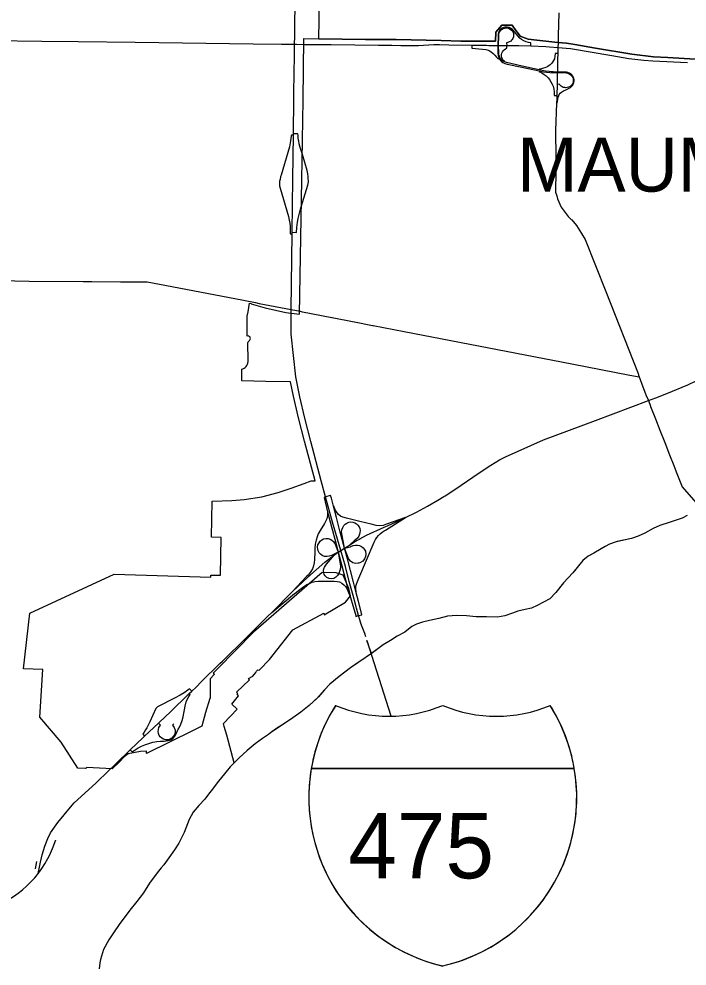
# Model space of a CAD drawing. Extents: x 0 to 750, y 0 to 507.
# Drawn here: x 229.9 to 276.3, y 149.3 to 215 of the extents above; entities that cross this region are included whole.
import ezdxf

# ---------------------------------------------------------------- set-up
doc = ezdxf.new("R2010")
doc.units = 0
for name, color, linetype in [('DV_X_Corp_Line', 7, 'Continuous'), ('GM_X_Corporation_Text', 7, 'Continuous'), ('GM_X_County', 7, 'Continuous'), ('GM_X_Interchange_Ramps', 7, 'Continuous'), ('GM_X_Interstate_Route', 7, 'Continuous'), ('GM_X_Rail_Line', 7, 'Continuous'), ('GM_X_US_Route', 7, 'Continuous')]:
    doc.layers.add(name, color=color, linetype=linetype)

msp = doc.modelspace()

# ---------------------------------------------------------------- linework, layer by layer
at = {"layer": 'DV_X_Corp_Line'}
for points in [[(277.58, 212.124), (274.932, 212.279), (273.94, 212.324), (272.425, 212.512), (269.916, 212.931), (268.479, 213.175), (267.91, 213.278), (267.311, 213.321), (265.848, 213.475), (265.244, 213.563), (264.866, 213.703), (264.697, 213.771), (264.564, 213.913), (264.382, 214.161), (264.137, 214.52), (263.427, 214.529), (263.001, 214.043), (262.967, 213.425), (260.563, 213.423), (259.202, 213.461), (256.08, 213.529), (253.965, 213.526), (250.728, 213.571), (250.775, 216.198)], [(276.279, 180.529), (275.922, 180.353), (275.013, 180.042), (274.386, 179.848), (273.909, 179.643), (273.335, 179.308), (272.872, 179.097), (272.407, 178.947), (271.468, 178.741), (271.428, 178.732), (271.278, 178.683), (270.876, 178.553), (270.585, 178.396), (269.8, 177.934), (269.402, 177.717), (269.028, 177.41), (268.729, 177.047), (268.466, 176.709), (268.349, 176.559), (267.696, 175.864), (267.153, 175.198), (266.758, 174.761), (265.878, 174.294), (265.466, 174.118), (265.03, 174.023), (264.524, 173.893), (264.152, 173.762), (263.625, 173.572), (263.109, 173.493), (262.354, 173.501), (261.644, 173.514), (260.97, 173.572), (260.29, 173.595), (259.655, 173.557), (259.058, 173.393), (258.407, 173.25), (257.905, 173.135), (257.494, 173.009), (257.172, 172.832), (256.688, 172.441), (256.159, 172.161), (255.696, 171.88), (255.183, 171.57), (254.361, 170.947), (253.529, 170.396), (252.915, 169.985), (252.133, 169.377), (251.492, 168.843), (251.112, 168.456), (250.585, 167.86), (250.06, 167.374), (249.475, 166.899), (248.91, 166.499), (248.49, 166.216), (248.331, 166.109), (247.469, 165.531), (247.232, 165.359), (246.809, 165.083), (246.305, 164.702), (245.75, 164.242), (245.204, 163.746), (244.845, 163.383), (244.334, 165.314), (244.149, 165.919), (244.109, 166.124), (245.056, 167.108), (244.695, 167.455), (245.161, 168.031), (245.042, 168.153), (245.096, 168.206), (245.023, 168.281), (245.922, 169.151), (245.848, 169.227), (246.148, 169.396), (246.36, 169.66), (246.393, 169.754), (246.503, 169.83), (246.597, 169.802), (246.597, 169.839), (247.304, 170.547), (248.919, 172.617), (251.077, 173.765), (251.083, 173.64), (252.564, 174.531), (252.916, 174.966), (252.8, 175.472), (252.405, 176.395), (251.933, 176.568), (250.96, 176.595), (246.203, 172.449), (243.694, 169.916), (243.39, 169.606), (243.456, 169.557), (243.471, 169.52), (243.176, 169.209), (243.176, 167.881), (243.156, 167.858), (242.87, 166.873), (242.613, 165.938), (242.003, 165.632), (238.774, 164.046), (238.777, 164.189), (238.365, 164.183), (237.507, 164.003), (237.223, 163.803), (236.871, 163.43), (236.389, 162.984), (234.624, 163.064), (234.591, 163.026), (234.526, 162.996), (233.997, 163.012), (232.849, 164.816), (231.372, 166.563), (231.578, 169.854), (230.229, 169.91), (230.671, 173.758), (236.519, 176.479), (243.237, 176.261), (243.237, 176.391), (243.908, 176.391), (243.958, 179), (243.284, 179.023), (243.329, 181.538), (244.697, 181.579), (245.548, 181.638), (246.773, 181.821), (247.905, 182.133), (248.816, 182.42), (249.711, 182.758), (250.192, 182.946), (250.46, 182.94), (249.733, 185.697), (249.314, 187.306), (248.963, 188.804), (248.749, 189.802), (247.04, 189.832), (245.383, 189.861), (245.383, 190.673), (245.462, 190.703), (245.533, 190.742), (245.603, 190.793), (245.675, 190.865), (245.729, 190.939), (245.769, 191.014), (245.801, 191.102), (245.822, 191.211), (245.824, 191.292), (245.822, 191.324), (245.802, 192.454), (245.802, 192.479), (245.808, 192.519), (245.82, 192.559), (245.84, 192.598), (245.866, 192.633), (245.887, 192.654), (245.919, 192.677), (245.943, 192.704), (245.962, 192.74), (245.971, 192.767), (245.975, 192.81), (245.967, 192.857), (245.952, 192.892), (245.93, 192.923), (245.902, 192.948), (245.859, 192.97), (245.816, 192.98), (245.764, 192.977), (245.745, 194.094), (245.745, 194.231), (245.753, 194.36), (245.82, 194.653), (245.916, 195.255), (246.022, 195.236), (246.02, 195.211), (247.003, 194.929), (248.434, 194.597), (249.39, 194.496), (249.54, 203.782), (249.626, 209.321), (249.682, 213.598), (250.728, 213.571), (253.965, 213.526), (256.08, 213.529), (259.202, 213.461), (260.563, 213.423), (262.967, 213.425), (263.001, 214.043), (263.427, 214.529), (264.137, 214.52), (264.382, 214.161), (264.564, 213.913), (264.697, 213.771), (264.866, 213.703), (265.244, 213.563), (265.848, 213.475), (267.311, 213.321), (267.91, 213.278), (268.479, 213.175), (269.916, 212.931), (272.425, 212.512), (273.94, 212.324), (274.932, 212.279), (277.58, 212.124)]]:
    msp.add_lwpolyline(points, dxfattribs=at)
at = {"layer": 'GM_X_County'}
msp.add_lwpolyline([(276.279, 180.529), (275.922, 180.353), (275.013, 180.042), (274.386, 179.848), (273.909, 179.643), (273.335, 179.308), (272.872, 179.097), (272.406, 178.947), (271.428, 178.732), (270.876, 178.553), (270.585, 178.396), (269.915, 177.997), (269.402, 177.717), (269.028, 177.41), (268.729, 177.047), (268.349, 176.559), (267.696, 175.864), (267.153, 175.198), (266.758, 174.761), (265.878, 174.294), (265.466, 174.118), (265.03, 174.023), (264.524, 173.893), (264.152, 173.762), (263.625, 173.572), (263.109, 173.493), (262.354, 173.501), (261.644, 173.514), (260.97, 173.572), (260.29, 173.595), (259.655, 173.557), (259.058, 173.393), (258.407, 173.25), (257.905, 173.135), (257.494, 173.009), (257.172, 172.832), (256.688, 172.441), (256.159, 172.161), (255.696, 171.88), (255.183, 171.57), (254.385, 170.966), (253.565, 170.42), (253.425, 170.326), (252.915, 169.985), (252.133, 169.377), (251.492, 168.843), (251.112, 168.456), (250.702, 167.968), (250.06, 167.374), (249.475, 166.899), (248.91, 166.499), (248.331, 166.109), (247.797, 165.769), (247.469, 165.531), (247.232, 165.359), (246.809, 165.083), (246.305, 164.702), (245.75, 164.242), (245.204, 163.746), (244.845, 163.383), (244.567, 163.101), (244.176, 162.634), (243.765, 162.117), (243.263, 161.44), (243.082, 161.209), (242.811, 160.863), (242.406, 160.442), (242.006, 159.959), (241.74, 159.456), (241.38, 158.557), (241.017, 157.829), (240.716, 157.37), (240.32, 156.798), (239.969, 156.33), (239.787, 156.105), (239.503, 155.754), (238.975, 155.037), (238.572, 154.385), (238.09, 153.783), (237.608, 153.176), (236.867, 152.176), (236.485, 151.604), (236.155, 151.111), (235.777, 150.458), (235.574, 149.768), (235.544, 149.53), (235.492, 149.117)], dxfattribs=at)
at = {"layer": 'GM_X_Interchange_Ramps'}
for points in [[(265.434, 213.085), (265.425, 213.31), (265.265, 213.335), (265.115, 213.368), (264.94, 213.433), (264.784, 213.529), (264.663, 213.629), (264.151, 214.221), (264.053, 214.299), (263.924, 214.364), (263.777, 214.395), (263.634, 214.388), (263.498, 214.348), (263.385, 214.288), (263.28, 214.197), (263.226, 214.103), (263.191, 214.019), (263.166, 213.901), (263.155, 213.796), (263.142, 213.118), (263.144, 212.561), (263.154, 212.448), (263.186, 212.326), (263.226, 212.239), (263.261, 212.17), (263.32, 212.081), (263.397, 212.006), (263.494, 211.94), (263.623, 211.879), (263.793, 211.824), (264.801, 211.611), (266.006, 211.357), (266.317, 211.292), (266.514, 211.26), (266.74, 211.241), (266.985, 211.231), (267.267, 211.239), (267.886, 211.217), (268.009, 211.193), (268.09, 211.156), (268.163, 211.106), (268.234, 211.045), (268.289, 210.974), (268.333, 210.893), (268.363, 210.798), (268.374, 210.707), (268.363, 210.608), (268.335, 210.503), (268.287, 210.405), (268.224, 210.343), (268.149, 210.274), (268.036, 210.223), (267.94, 210.203), (267.868, 210.191), (267.791, 210.193), (267.679, 210.207), (267.6, 210.25), (267.53, 210.304), (267.453, 210.375), (267.404, 210.434), (267.248, 210.422)], [(267.216, 209.11), (267.266, 209.109), (267.277, 209.242), (267.295, 209.4), (267.327, 209.541), (267.368, 209.649), (267.4, 209.725), (267.453, 209.802), (267.556, 209.883), (267.706, 209.966), (267.866, 210.037), (268.175, 210.201), (268.266, 210.292), (268.332, 210.367), (268.374, 210.444), (268.406, 210.543), (268.428, 210.654), (268.426, 210.758), (268.406, 210.841), (268.376, 210.924), (268.337, 210.996), (268.276, 211.079), (268.2, 211.15), (268.104, 211.205), (267.999, 211.241), (267.896, 211.26), (267.268, 211.275), (266.983, 211.286), (266.848, 211.294), (266.69, 211.304), (266.455, 211.332), (266.012, 211.426), (264.822, 211.693), (263.742, 211.935), (263.555, 211.998), (263.464, 212.055), (263.385, 212.136), (263.32, 212.225), (263.251, 212.355), (263.213, 212.468), (263.203, 212.579), (263.176, 213.118), (263.206, 213.774), (263.22, 213.896), (263.242, 214.007), (263.302, 214.114), (263.378, 214.201), (263.44, 214.246), (263.516, 214.293), (263.623, 214.326), (263.757, 214.335), (263.872, 214.31), (263.984, 214.259), (264.082, 214.183), (264.169, 214.081), (264.218, 213.958), (264.236, 213.845), (264.224, 213.718), (264.18, 213.606), (264.14, 213.531), (264.097, 213.475), (264.013, 213.399), (263.935, 213.361), (263.839, 213.328), (263.748, 213.308), (263.762, 213.115)], [(261.33, 213.142), (261.325, 212.928), (262.075, 212.871), (262.316, 212.836), (262.476, 212.782), (262.563, 212.741), (262.688, 212.674), (262.824, 212.565), (262.943, 212.452), (263.053, 212.31), (263.162, 212.197), (263.226, 212.239)], [(263.555, 211.998), (263.591, 212.047), (263.54, 212.083), (263.468, 212.164), (263.417, 212.274), (263.393, 212.385), (263.393, 212.49), (263.423, 212.595), (263.47, 212.682), (263.528, 212.763), (263.589, 212.814), (263.676, 212.883), (263.772, 212.927), (263.762, 213.115)], [(267.298, 212.558), (267.112, 212.563), (267.092, 212.369), (267.069, 212.182), (267.011, 212.069), (266.941, 211.964), (266.858, 211.869), (266.773, 211.772), (266.698, 211.723), (266.615, 211.67), (266.522, 211.616), (266.408, 211.563), (266.299, 211.533), (266.172, 211.5), (266.038, 211.486), (266.012, 211.426)], [(266.006, 211.357), (265.994, 211.303), (266.194, 211.229), (266.358, 211.116), (266.483, 211.017), (266.625, 210.869), (266.722, 210.75), (266.819, 210.594), (266.898, 210.446), (266.975, 210.286), (267.034, 210.086), (267.048, 209.902), (267.044, 209.729), (267.047, 209.655), (267.229, 209.65)], [(248.96, 206.892), (248.822, 206.894), (248.816, 206.833), (248.76, 206.496), (248.679, 206.086), (248.11, 204.117), (248.073, 204.032)], [(249.999, 203.675), (250.004, 203.75), (249.994, 203.86), (249.985, 204.032), (249.964, 204.217), (249.913, 204.439), (249.581, 205.559), (249.434, 206.053), (249.371, 206.288), (249.332, 206.485), (249.299, 206.689), (249.279, 206.91), (249.277, 206.997), (248.962, 207.001)], [(248.073, 204.032), (248.032, 203.824), (248.005, 203.708), (247.996, 203.561), (248.005, 203.395), (248.038, 203.228), (248.609, 201.268), (248.671, 201.003), (248.716, 200.811), (248.731, 200.59), (248.746, 200.065), (248.872, 200.064)], [(248.873, 200.168), (249.176, 200.164), (249.202, 200.494), (249.252, 200.862), (249.301, 201.132), (249.402, 201.591), (249.502, 201.923), (249.955, 203.436), (249.999, 203.675)], [(253.484, 173.592), (253.7, 173.656), (253.655, 173.862), (253.475, 174.57), (253.295, 175.278), (253.13, 175.925), (252.707, 177.523), (252.508, 178.275), (252.213, 179.39), (251.949, 180.389), (251.739, 181.186), (251.594, 181.74), (251.539, 181.914), (251.195, 181.819)], [(251.195, 181.819), (251.086, 181.784), (251.335, 180.787), (251.606, 179.747), (251.898, 178.645), (252.072, 177.992), (252.323, 177.047), (252.722, 175.544), (253.279, 173.592), (253.298, 173.529), (253.484, 173.592)], [(251.335, 180.787), (251.316, 180.782), (251.326, 180.677), (251.319, 180.53), (251.269, 180.31), (251.207, 180.163), (251.106, 179.979), (250.814, 179.505), (250.68, 179.254), (250.606, 179.047), (250.534, 178.818), (250.474, 178.542), (250.446, 178.278), (250.438, 178.01), (250.422, 177.489), (250.392, 177.247), (250.345, 177.04), (250.273, 176.838), (250.17, 176.642), (250.06, 176.483), (249.979, 176.406), (249.878, 176.303), (248.905, 175.263)], [(256.731, 180.4), (255.426, 179.937), (255.192, 179.851), (254.96, 179.823), (254.703, 179.847), (254.344, 179.924), (253.575, 180.112), (252.648, 180.339), (252.396, 180.42), (252.226, 180.496), (252.088, 180.597), (251.985, 180.714), (251.901, 180.854), (251.83, 180.997), (251.759, 181.192), (251.739, 181.186)], [(252.508, 178.275), (252.299, 179.413), (252.319, 179.552), (252.377, 179.711), (252.455, 179.841), (252.553, 179.94), (252.667, 180.01), (252.81, 180.068), (252.951, 180.086), (253.081, 180.076), (253.215, 180.026), (253.332, 179.956), (253.425, 179.867), (253.513, 179.751), (253.558, 179.638), (253.585, 179.504), (253.578, 179.361), (253.546, 179.237), (253.493, 179.102), (253.405, 178.975), (253.289, 178.866), (253.227, 178.815), (252.841, 178.482)], [(253.295, 175.278), (253.311, 175.282), (253.28, 175.426), (253.28, 175.517), (253.29, 175.634), (253.332, 175.777), (253.399, 175.967), (253.494, 176.189), (254.565, 178.691), (254.662, 178.874), (254.748, 179.001), (254.867, 179.144), (254.985, 179.267), (255.118, 179.371), (255.247, 179.466), (255.338, 179.52), (256.731, 180.4)], [(252.072, 177.992), (251.788, 177.856), (251.595, 177.762), (251.443, 177.706), (251.293, 177.682), (251.122, 177.7), (250.96, 177.755), (250.842, 177.849), (250.751, 177.953), (250.679, 178.077), (250.646, 178.205), (250.634, 178.349), (250.659, 178.492), (250.736, 178.647), (250.827, 178.761), (250.932, 178.849), (251.049, 178.909), (251.22, 178.947), (251.375, 178.934), (251.518, 178.897), (251.629, 178.833), (251.735, 178.733), (251.822, 178.625), (251.823, 178.624), (252.072, 177.992)], [(252.072, 177.992), (252.232, 177.023), (252.224, 176.892), (252.185, 176.721), (252.11, 176.515), (252.017, 176.375), (251.898, 176.256), (251.757, 176.177), (251.573, 176.148), (251.43, 176.164), (251.276, 176.244), (251.173, 176.342), (251.098, 176.453), (251.062, 176.578), (251.053, 176.728), (251.076, 176.847), (251.124, 176.96), (251.206, 177.083), (251.266, 177.158), (251.816, 177.815)], [(252.508, 178.275), (252.916, 178.361), (252.948, 178.378), (253.103, 178.449), (253.263, 178.479), (253.412, 178.482), (253.551, 178.451), (253.687, 178.386), (253.8, 178.297), (253.876, 178.194), (253.951, 178.055), (253.987, 177.865), (253.966, 177.691), (253.897, 177.529), (253.769, 177.371), (253.611, 177.266), (253.506, 177.237), (253.459, 177.223), (253.265, 177.208), (253.083, 177.259), (252.921, 177.368), (252.817, 177.49), (252.782, 177.543), (252.508, 178.275)], [(247.457, 173.816), (249.042, 175.127), (249.081, 175.16), (249.407, 175.407), (249.68, 175.61), (249.893, 175.745), (250.075, 175.829), (250.266, 175.904), (250.452, 175.949), (250.689, 175.974), (250.978, 175.979), (251.798, 175.993), (251.996, 175.967), (252.155, 175.927), (252.319, 175.848), (252.452, 175.739), (252.575, 175.608), (252.66, 175.482), (252.737, 175.318), (252.9, 174.927)], [(241.911, 168.355), (241.755, 168.517), (241.636, 168.424), (241.391, 168.248), (241.099, 168.074), (240.765, 167.891), (239.543, 167.274), (239.506, 167.238)], [(241.034, 165.813), (241.054, 165.867), (241.152, 166.07), (241.25, 166.319), (241.31, 166.568), (241.363, 166.831), (241.4, 167.065), (241.445, 167.321), (241.528, 167.615), (241.619, 167.834), (241.702, 167.999), (241.792, 168.135), (241.74, 168.189)], [(239.506, 167.238), (239.418, 167.151), (239.008, 166.242), (238.888, 166), (238.802, 165.824), (238.711, 165.667), (238.619, 165.523), (238.506, 165.368), (238.635, 165.23)], [(240.67, 166.096), (240.584, 166.006), (240.697, 165.837), (240.752, 165.65), (240.749, 165.493), (240.705, 165.327), (240.629, 165.206), (240.534, 165.103), (240.4, 165.033), (240.254, 164.994), (240.088, 164.987), (239.944, 165.021), (239.826, 165.088), (239.724, 165.183), (239.65, 165.282), (239.595, 165.419), (239.575, 165.559), (239.591, 165.703), (239.625, 165.833), (239.73, 165.99), (239.732, 165.992), (239.596, 166.136)], [(237.643, 164.293), (237.777, 164.15), (237.983, 164.3), (238.202, 164.431), (238.422, 164.544), (238.661, 164.643), (238.941, 164.74), (239.202, 164.811), (239.489, 164.857), (239.744, 164.884), (240.005, 164.897), (240.27, 164.927), (240.467, 164.992), (240.617, 165.091), (240.728, 165.228), (240.794, 165.359), (240.975, 165.714), (241.034, 165.813)]]:
    msp.add_lwpolyline(points, dxfattribs=at)
at = {"layer": 'GM_X_Interstate_Route'}
for p, q in [((250.2, 162.997), (268.443, 162.997)), ((268.443, 162.997), (250.2, 162.997)), ((268.443, 162.997), (250.2, 162.997))]:
    msp.add_line(p, q, dxfattribs=at)
for points in [[(249.053, 214.099), (249.053, 214.125), (249.076, 216.406), (249.111, 220.891)], [(249.047, 213.459), (249.048, 213.505), (249.053, 214.099)], [(228.091, 213.464), (231.52, 213.427), (234.026, 213.397)], [(234.026, 213.397), (237.986, 213.349), (246.163, 213.231), (248.141, 213.214), (248.646, 213.208)], [(249.028, 212.001), (249.045, 213.202), (249.047, 213.459)], [(248.646, 213.208), (249.045, 213.202), (249.185, 213.2)], [(249.185, 213.2), (249.71, 213.193), (249.748, 213.193)], [(249.748, 213.193), (250.652, 213.181), (251.577, 213.178), (254.868, 213.135), (255.791, 213.132), (256.415, 213.124), (257.639, 213.117), (258.694, 213.176), (259.091, 213.18), (259.748, 213.162), (261.33, 213.142), (262.354, 213.128)], [(262.354, 213.128), (262.519, 213.126), (263.142, 213.118), (263.176, 213.118), (263.762, 213.115), (264.23, 213.113), (264.591, 213.108), (265.434, 213.085), (266.474, 213.048), (266.734, 213.026), (267.308, 212.976)], [(267.308, 212.976), (267.308, 212.976), (268.181, 212.899), (271.038, 212.415), (272.232, 212.218), (273.265, 212.094), (273.891, 212.054), (276.294, 211.937)], [(248.92, 203.873), (248.96, 206.892), (248.962, 207.001), (248.994, 209.416), (249.023, 211.596)], [(249.023, 211.596), (249.023, 211.601), (249.028, 212.001)], [(248.808, 194.811), (248.872, 200.064), (248.873, 200.168), (248.895, 202.032), (248.92, 203.873)], [(248.808, 194.545), (248.808, 194.811)], [(250.887, 182.93), (250.167, 185.662), (249.748, 187.272), (249.397, 188.77), (249.138, 190.155), (248.81, 193.103), (248.808, 194.545)], [(252.251, 178.115), (251.68, 180.07), (251.195, 181.819), (250.887, 182.93)], [(253.268, 174.366), (253.265, 174.378), (253.107, 174.998), (252.827, 175.969), (252.581, 176.995), (252.251, 178.115)], [(253.338, 174.107), (253.334, 174.121), (253.311, 174.198), (253.268, 174.366)], [(253.594, 173.219), (253.592, 173.227), (253.484, 173.592), (253.338, 174.107)], [(253.98, 172.121), (253.909, 172.344), (253.673, 172.934), (253.594, 173.219)], [(254.385, 170.966), (254.182, 171.483), (254.058, 171.874), (255.711, 166.651)]]:
    msp.add_lwpolyline(points, dxfattribs=at)
for centre, radius, start, end in [((262.02, 160.988), 11.99, 147.82161, 256.99413), ((261.271, 161.196), 11.216, 146.65397, 170.75899), ((255.598, 176.186), 9.567, 247.08482, 292.91053), ((255.598, 176.186), 9.567, 247.08482, 292.91053), ((256.624, 160.988), 11.989, 283.00654, 32.17868), ((263.047, 176.187), 9.569, 247.09162, 292.90836), ((263.047, 176.187), 9.569, 247.09162, 292.90836), ((256.623, 160.988), 11.99, 9.64753, 32.17902), ((262.02, 160.988), 11.989, 170.35136, 256.9967), ((256.648, 160.983), 11.966, 282.76665, 9.68983)]:
    msp.add_arc(centre, radius, start, end, dxfattribs=at)
at = {"layer": 'GM_X_Rail_Line'}
msp.add_lwpolyline([(231.069, 156.053), (231.161, 156.544)], dxfattribs=at)
at = {"layer": 'GM_X_US_Route'}
for points in [[(267.363, 215.384), (267.326, 213.779)], [(267.32, 213.511), (267.32, 213.501), (267.315, 213.266), (267.308, 212.976), (267.305, 212.837)], [(267.326, 213.779), (267.326, 213.764), (267.32, 213.511)], [(267.305, 212.837), (267.298, 212.558), (267.289, 212.158)], [(267.289, 212.158), (267.268, 211.275), (267.267, 211.239), (267.248, 210.422), (267.229, 209.65), (267.223, 209.38)], [(267.22, 209.245), (267.216, 209.11), (267.139, 207.227)], [(267.223, 209.38), (267.221, 209.283), (267.22, 209.245)], [(267.139, 207.227), (267.133, 207.093), (267.174, 205.441), (267.174, 205.435)], [(267.174, 205.435), (267.17, 204), (267.147, 203.395)], [(267.144, 203.13), (267.142, 202.952), (267.221, 202.699), (267.271, 202.477), (267.533, 201.92), (268.023, 201.252), (268.222, 201.063)], [(267.147, 203.395), (267.144, 203.13)], [(268.222, 201.063), (268.262, 201.026), (268.603, 200.647), (268.95, 200.072), (269.201, 199.67), (270.624, 196.062), (272.875, 190.387), (272.904, 190.274), (272.905, 190.27)], [(217.09, 196.951), (217.222, 196.949), (222.824, 196.937), (224.094, 196.934), (225.678, 196.897), (230.62, 196.785), (234.366, 196.758), (234.743, 196.756), (234.983, 196.754)], [(234.983, 196.754), (236.955, 196.741), (237.672, 196.738), (237.756, 196.737)], [(237.756, 196.737), (238.805, 196.733), (240.527, 196.404), (245.5, 195.451), (246.332, 195.291), (246.593, 195.241), (246.593, 195.241)], [(246.593, 195.241), (248.808, 194.811)], [(248.808, 194.811), (249.419, 194.693), (249.578, 194.662)], [(249.578, 194.662), (249.582, 194.661), (251.631, 194.264)], [(251.631, 194.264), (251.646, 194.261), (253.17, 193.965)], [(253.17, 193.965), (253.194, 193.961), (254.453, 193.716)], [(254.453, 193.716), (254.483, 193.71), (256.638, 193.293), (268.263, 191.037)], [(268.263, 191.037), (272.288, 190.266)], [(274.858, 189.002), (274.858, 189.002), (276.329, 189.585), (276.905, 189.873), (277.19, 190.044), (277.229, 190.067), (277.623, 190.423)], [(272.288, 190.266), (272.292, 190.265), (272.937, 190.141)], [(272.905, 190.27), (272.937, 190.141), (273.196, 189.451), (273.38, 188.963), (273.381, 188.96)], [(266.317, 185.781), (269.917, 187.127), (273.583, 188.497)], [(273.381, 188.96), (273.395, 188.923), (273.402, 188.904), (273.583, 188.497)], [(273.583, 188.497), (274.093, 188.699)], [(273.583, 188.497), (273.73, 188.122)], [(274.093, 188.699), (274.858, 189.002)], [(273.73, 188.122), (273.74, 188.098), (274.078, 187.234), (274.387, 186.447), (274.723, 185.59), (275.055, 184.743), (275.345, 184.002)], [(259.485, 181.909), (260.168, 182.346), (261.838, 183.492), (262.645, 184.029), (263.259, 184.389), (263.674, 184.607), (266.317, 185.781)], [(275.345, 184.002), (275.419, 183.813), (275.518, 183.561), (275.93, 182.511), (278.962, 179.055)], [(258.989, 181.609), (259.397, 181.853), (259.485, 181.909)], [(253.492, 178.882), (253.568, 178.928), (254.037, 179.166), (255.252, 179.721), (255.482, 179.823), (256.731, 180.4), (257.49, 180.766), (258.267, 181.177), (258.989, 181.609)], [(251.925, 177.89), (252.072, 177.992), (252.251, 178.115), (252.508, 178.275), (252.841, 178.482), (253.269, 178.747), (253.38, 178.815)], [(253.38, 178.815), (253.492, 178.882)], [(247.457, 173.816), (248.905, 175.263), (249.934, 176.244), (251.15, 177.302), (251.816, 177.815), (251.925, 177.89)], [(243.862, 170.265), (244.044, 170.442), (244.1, 170.498), (245.623, 171.99), (247.191, 173.551), (247.457, 173.816)], [(242.594, 169.023), (243.862, 170.265)], [(242.204, 168.641), (242.594, 169.023)], [(238.536, 165.136), (238.635, 165.23), (239.596, 166.136), (240.114, 166.625), (240.382, 166.877), (241.74, 168.189), (241.911, 168.355), (242.204, 168.641)], [(237.577, 164.23), (237.643, 164.293), (238.536, 165.136)], [(235.941, 162.651), (237.577, 164.23)], [(235.344, 162.073), (235.464, 162.19), (235.941, 162.651)], [(231.486, 156.808), (231.531, 157.023), (231.709, 157.606), (231.936, 158.137), (232.1, 158.535), (232.63, 159.246), (233.504, 160.305), (233.761, 160.626), (235.255, 161.988), (235.344, 162.073)], [(231.254, 155.71), (231.372, 156.267), (231.42, 156.496), (231.486, 156.808)]]:
    msp.add_lwpolyline(points, dxfattribs=at)
msp.add_arc((225.597, 160.102), 7.162, 284.08609, 335.3259, dxfattribs=at)
msp.add_spline([(232.105, 157.112), (232.111, 157.124), (232.116, 157.136), (232.122, 157.149), (232.128, 157.161), (232.133, 157.173), (232.139, 157.186), (232.144, 157.198), (232.15, 157.21), (232.155, 157.223), (232.161, 157.235), (232.166, 157.247), (232.171, 157.26), (232.177, 157.272), (232.182, 157.285), (232.187, 157.297), (232.193, 157.31), (232.198, 157.322), (232.203, 157.334), (232.209, 157.347), (232.214, 157.359), (232.219, 157.372), (232.224, 157.384), (232.229, 157.397), (232.235, 157.409), (232.24, 157.422), (232.245, 157.434), (232.25, 157.447), (232.255, 157.459), (232.26, 157.472), (232.265, 157.484), (232.27, 157.497), (232.275, 157.509), (232.281, 157.522), (232.286, 157.534), (232.291, 157.547), (232.296, 157.559), (232.301, 157.572), (232.306, 157.585), (232.311, 157.597), (232.316, 157.61), (232.32, 157.622), (232.325, 157.635), (232.33, 157.647), (232.335, 157.66), (232.34, 157.673), (232.345, 157.685), (232.35, 157.698), (232.355, 157.71), (232.36, 157.723), (232.365, 157.736), (232.369, 157.748), (232.374, 157.761), (232.379, 157.773), (232.384, 157.786), (232.389, 157.799), (232.394, 157.811), (232.398, 157.824), (232.403, 157.837), (232.408, 157.849), (232.413, 157.862), (232.418, 157.874), (232.422, 157.887), (232.427, 157.9), (232.432, 157.912), (232.437, 157.925), (232.442, 157.938), (232.446, 157.95), (232.451, 157.963), (232.456, 157.976), (232.461, 157.988), (232.466, 158.001), (232.47, 158.013), (232.475, 158.026), (232.48, 158.039)], degree=3, dxfattribs=at)

# ---------------------------------------------------------------- texts
at = {"layer": 'GM_X_Corporation_Text'}
msp.add_text('MAUMEE', height=3.7501, rotation=0.00001, dxfattribs=at).set_placement((264.484, 202.984))
at = {"layer": 'GM_X_Interstate_Route'}
msp.add_text('475', height=4.5281, dxfattribs=at).set_placement((252.768, 155.383))

doc.saveas('drawing.dxf')
